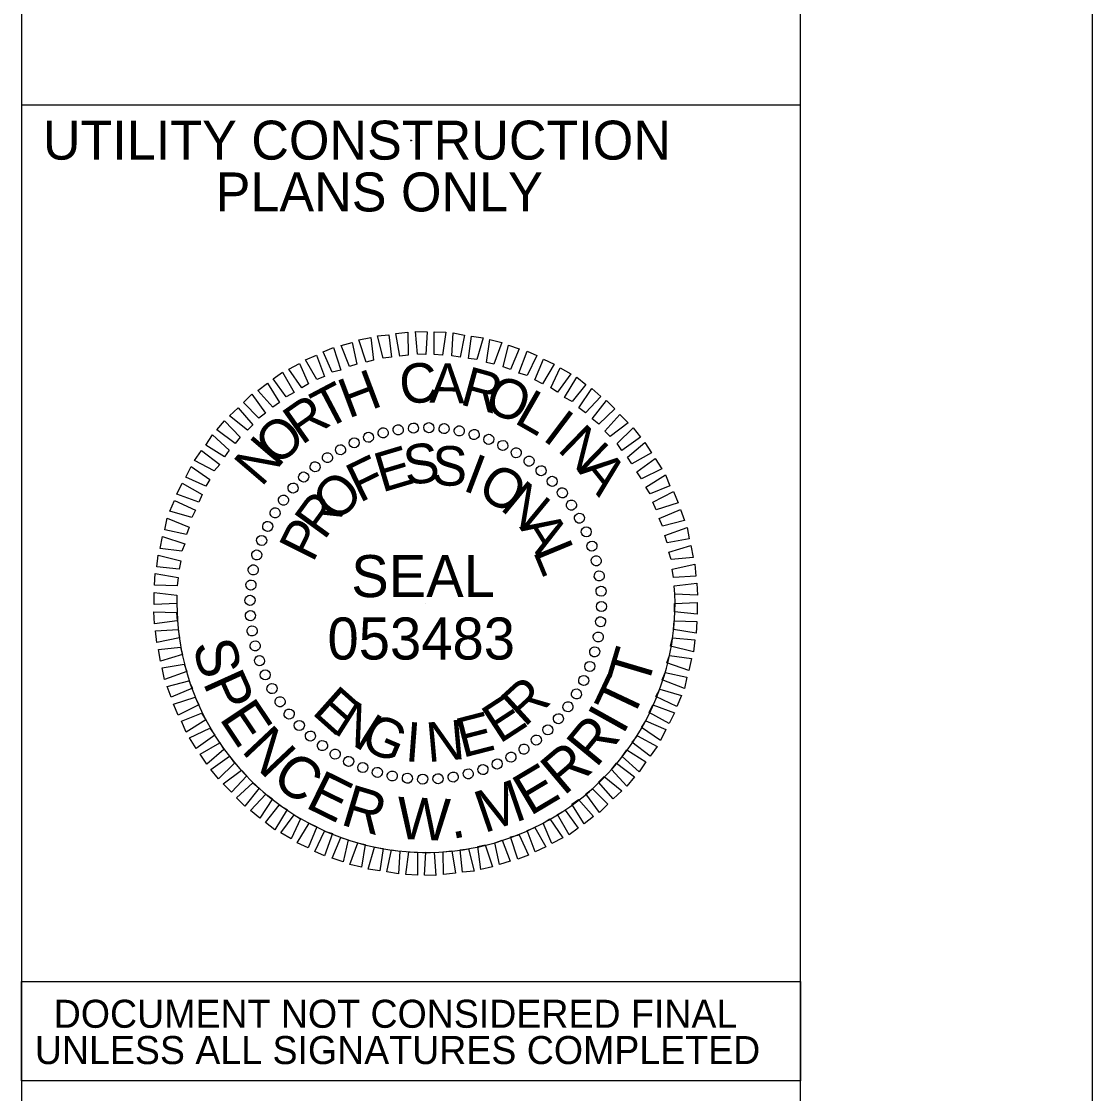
# Model space of a CAD drawing. Extents: x -0.32 to 3.05, y 0 to 1.83.
# Drawn here: x 2.6041 to 2.8333, y 1.3744 to 1.6039 of the extents above; entities that cross this region are included whole.
import ezdxf

# ---------------------------------------------------------------- set-up
doc = ezdxf.new("R2010")
doc.units = 0
for name, color, linetype in [('E_NCDOT_Terrain_Model_Contour_Minor', 7, 'Continuous'), ('P_NCDOT_Terrain_Model_Triangles', 7, 'Continuous'), ('P_RDY_TL_Draft_DNC_Null_Point', 7, 'Continuous'), ('P_RDY_TL_Grass_Shoulder_Normal', 7, 'Continuous')]:
    doc.layers.add(name, color=color, linetype=linetype)

msp = doc.modelspace()

# ---------------------------------------------------------------- linework, layer by layer
at = {"layer": 'E_NCDOT_Terrain_Model_Contour_Minor'}
msp.add_arc((2.69065, 1.4793), 0.05331, 180.0118, 2.0847, dxfattribs=at)
at = {"layer": 'P_NCDOT_Terrain_Model_Triangles'}
for p, q in [((2.68797, 1.51686), (2.68797, 1.51686)), ((2.69127, 1.51694), (2.69127, 1.51694)), ((2.6783, 1.51491), (2.6783, 1.51491)), ((2.68145, 1.51581), (2.68145, 1.51581)), ((2.68475, 1.51641), (2.68475, 1.51641)), ((2.69457, 1.51671), (2.69457, 1.51671)), ((2.6978, 1.51619), (2.6978, 1.51619)), ((2.70095, 1.51551), (2.70095, 1.51551)), ((2.6753, 1.51371), (2.6753, 1.51371)), ((2.7041, 1.51446), (2.7041, 1.51446)), ((2.7071, 1.51311), (2.7071, 1.51311)), ((2.66952, 1.51049), (2.66952, 1.51049)), ((2.67237, 1.51221), (2.67237, 1.51221)), ((2.71002, 1.51161), (2.71002, 1.51161)), ((2.6669, 1.50861), (2.6669, 1.50861)), ((2.71272, 1.50974), (2.71272, 1.50974)), ((2.71535, 1.50771), (2.71535, 1.50771)), ((2.66442, 1.50636), (2.66442, 1.50636)), ((2.71767, 1.50546), (2.71767, 1.50546)), ((2.66217, 1.50404), (2.66217, 1.50404)), ((2.66015, 1.50141), (2.66015, 1.50141)), ((2.71992, 1.50299), (2.71992, 1.50299)), ((2.65827, 1.49871), (2.65827, 1.49871)), ((2.7218, 1.50036), (2.7218, 1.50036)), ((2.72352, 1.49751), (2.72352, 1.49751)), ((2.65677, 1.49579), (2.65677, 1.49579)), ((2.72502, 1.49459), (2.72502, 1.49459)), ((2.65542, 1.49279), (2.65542, 1.49279)), ((2.72622, 1.49159), (2.72622, 1.49159)), ((2.65437, 1.48964), (2.65437, 1.48964)), ((2.72712, 1.48844), (2.72712, 1.48844)), ((2.6537, 1.48649), (2.6537, 1.48649)), ((2.72772, 1.48514), (2.72772, 1.48514)), ((2.65317, 1.48326), (2.65317, 1.48326)), ((2.72817, 1.48191), (2.72817, 1.48191)), ((2.65295, 1.47996), (2.65295, 1.47996)), ((2.6906, 1.47929), (2.6906, 1.47929)), ((2.72825, 1.47861), (2.72825, 1.47861)), ((2.65302, 1.47666), (2.65302, 1.47666)), ((2.65347, 1.47344), (2.65347, 1.47344)), ((2.72802, 1.47531), (2.72802, 1.47531)), ((2.7275, 1.47209), (2.7275, 1.47209)), ((2.65407, 1.47014), (2.65407, 1.47014)), ((2.72682, 1.46894), (2.72682, 1.46894)), ((2.65497, 1.46699), (2.65497, 1.46699)), ((2.72577, 1.46579), (2.72577, 1.46579)), ((2.65617, 1.46399), (2.65617, 1.46399)), ((2.72442, 1.46279), (2.72442, 1.46279)), ((2.65767, 1.46106), (2.65767, 1.46106)), ((2.72292, 1.45986), (2.72292, 1.45986)), ((2.6594, 1.45821), (2.6594, 1.45821)), ((2.72105, 1.45716), (2.72105, 1.45716)), ((2.66127, 1.45559), (2.66127, 1.45559)), ((2.66352, 1.45311), (2.66352, 1.45311)), ((2.71902, 1.45454), (2.71902, 1.45454)), ((2.66585, 1.45086), (2.66585, 1.45086)), ((2.71677, 1.45221), (2.71677, 1.45221)), ((2.66847, 1.44884), (2.66847, 1.44884)), ((2.71167, 1.44809), (2.71167, 1.44809)), ((2.7143, 1.44996), (2.7143, 1.44996)), ((2.67117, 1.44696), (2.67117, 1.44696)), ((2.70882, 1.44636), (2.70882, 1.44636)), ((2.6741, 1.44546), (2.6741, 1.44546)), ((2.6771, 1.44411), (2.6771, 1.44411)), ((2.7029, 1.44366), (2.7029, 1.44366)), ((2.7059, 1.44486), (2.7059, 1.44486)), ((2.68025, 1.44306), (2.68025, 1.44306)), ((2.6834, 1.44239), (2.6834, 1.44239)), ((2.68662, 1.44186), (2.68662, 1.44186)), ((2.68992, 1.44164), (2.68992, 1.44164)), ((2.69322, 1.44171), (2.69322, 1.44171)), ((2.69645, 1.44216), (2.69645, 1.44216)), ((2.69975, 1.44276), (2.69975, 1.44276))]:
    msp.add_line(p, q, dxfattribs=at)
for points in [[(2.6888, 1.53261), (2.68842, 1.53749), (2.6909, 1.53741), (2.6906, 1.53254)], [(2.67785, 1.53096), (2.67627, 1.53569), (2.67882, 1.53621), (2.67942, 1.53134)], [(2.68145, 1.53179), (2.68025, 1.53659), (2.68272, 1.53681), (2.68325, 1.53201)], [(2.68505, 1.53224), (2.68422, 1.53704), (2.68677, 1.53734), (2.68685, 1.53246)], [(2.6924, 1.53254), (2.6924, 1.53741), (2.69487, 1.53734), (2.6942, 1.53246)], [(2.69615, 1.53231), (2.69645, 1.53719), (2.69892, 1.53674), (2.69795, 1.53201)], [(2.69975, 1.53171), (2.70042, 1.53651), (2.7029, 1.53614), (2.70155, 1.53149)], [(2.70357, 1.53089), (2.70432, 1.53576), (2.70687, 1.53516), (2.70515, 1.53051)], [(2.67057, 1.52879), (2.66862, 1.53314), (2.67087, 1.53404), (2.67245, 1.52924)], [(2.67425, 1.52999), (2.67252, 1.53449), (2.67485, 1.53516), (2.67582, 1.53051)], [(2.70717, 1.52991), (2.7083, 1.53456), (2.71062, 1.53381), (2.70875, 1.52939)], [(2.71055, 1.52856), (2.71227, 1.53329), (2.71437, 1.53239), (2.71227, 1.52804)], [(2.66405, 1.52541), (2.66127, 1.52946), (2.6636, 1.53066), (2.66547, 1.52631)], [(2.66727, 1.52721), (2.66487, 1.53141), (2.6672, 1.53246), (2.66892, 1.52789)], [(2.71392, 1.52714), (2.7158, 1.53156), (2.71812, 1.53051), (2.71557, 1.52631)], [(2.66075, 1.52354), (2.65797, 1.52736), (2.65992, 1.52879), (2.6624, 1.52444)], [(2.71737, 1.52541), (2.7194, 1.52969), (2.72165, 1.52841), (2.7188, 1.52451)], [(2.6579, 1.52129), (2.65467, 1.52489), (2.6567, 1.52646), (2.65932, 1.52226)], [(2.7203, 1.52339), (2.72292, 1.52774), (2.72487, 1.52616), (2.72195, 1.52249)], [(2.6549, 1.51896), (2.6516, 1.52226), (2.6534, 1.52406), (2.65632, 1.52001)], [(2.72337, 1.52114), (2.72615, 1.52526), (2.7281, 1.52361), (2.7248, 1.52009)], [(2.72622, 1.51881), (2.7293, 1.52271), (2.7311, 1.52091), (2.72765, 1.51769)], [(2.65242, 1.51634), (2.6486, 1.51941), (2.65047, 1.52114), (2.65362, 1.51754)], [(2.72892, 1.51619), (2.73215, 1.51971), (2.73395, 1.51791), (2.73005, 1.51499)], [(2.6498, 1.51349), (2.6459, 1.51641), (2.64755, 1.51836), (2.65085, 1.51484)], [(2.73155, 1.51349), (2.735, 1.51686), (2.73657, 1.51484), (2.7326, 1.51199)], [(2.64755, 1.51064), (2.6435, 1.51319), (2.64492, 1.51536), (2.64852, 1.51206)], [(2.7338, 1.51056), (2.73747, 1.51371), (2.7389, 1.51154), (2.7347, 1.50914)], [(2.6453, 1.50764), (2.6411, 1.50989), (2.6426, 1.51199), (2.6465, 1.50899)], [(2.73575, 1.50749), (2.73972, 1.51034), (2.74115, 1.50809), (2.7368, 1.50599)], [(2.6435, 1.50441), (2.63922, 1.50629), (2.64035, 1.50861), (2.6444, 1.50584)], [(2.7377, 1.50419), (2.7419, 1.50681), (2.74287, 1.50449), (2.7386, 1.50276)], [(2.642, 1.50096), (2.63735, 1.50269), (2.63847, 1.50501), (2.64275, 1.50261)], [(2.7392, 1.50096), (2.74362, 1.50321), (2.7446, 1.50081), (2.73995, 1.49931)], [(2.6405, 1.49766), (2.63585, 1.49901), (2.63682, 1.50134), (2.64132, 1.49924)], [(2.74055, 1.49744), (2.74512, 1.49939), (2.74595, 1.49706), (2.7413, 1.49586)], [(2.63937, 1.49406), (2.63472, 1.49504), (2.63525, 1.49751), (2.63997, 1.49564)], [(2.74175, 1.49384), (2.74655, 1.49556), (2.747, 1.49309), (2.74227, 1.49226)], [(2.6384, 1.49046), (2.63375, 1.49106), (2.63427, 1.49361), (2.639, 1.49204)], [(2.74265, 1.49024), (2.74737, 1.49166), (2.74782, 1.48911), (2.7431, 1.48866)], [(2.6378, 1.48664), (2.633, 1.48709), (2.6333, 1.48964), (2.63817, 1.48844)], [(2.74332, 1.48664), (2.7482, 1.48769), (2.74842, 1.48514), (2.74362, 1.48484)], [(2.63742, 1.48304), (2.63255, 1.48319), (2.6327, 1.48566), (2.63757, 1.48484)], [(2.74377, 1.48304), (2.74865, 1.48364), (2.7488, 1.48109), (2.74392, 1.48124)], [(2.63735, 1.47929), (2.63247, 1.47906), (2.63247, 1.48161), (2.63735, 1.48109)], [(2.74385, 1.47929), (2.74872, 1.47951), (2.74872, 1.47696), (2.74385, 1.47749)], [(2.63742, 1.47554), (2.63255, 1.47494), (2.6324, 1.47749), (2.63727, 1.47734)], [(2.74377, 1.47554), (2.74865, 1.47539), (2.7485, 1.47291), (2.74362, 1.47374)], [(2.63787, 1.47194), (2.633, 1.47089), (2.63277, 1.47344), (2.63757, 1.47374)], [(2.7434, 1.47194), (2.7482, 1.47149), (2.7479, 1.46894), (2.74302, 1.47014)], [(2.63855, 1.46834), (2.63382, 1.46691), (2.63337, 1.46946), (2.6381, 1.46991)], [(2.7428, 1.46811), (2.74745, 1.46751), (2.74692, 1.46496), (2.7422, 1.46654)], [(2.63945, 1.46474), (2.63465, 1.46301), (2.6342, 1.46549), (2.63892, 1.46631)], [(2.74182, 1.46451), (2.74647, 1.46354), (2.74595, 1.46106), (2.74122, 1.46294)], [(2.64065, 1.46114), (2.63607, 1.45919), (2.63525, 1.46151), (2.6399, 1.46271)], [(2.7407, 1.46091), (2.74535, 1.45956), (2.74437, 1.45724), (2.73987, 1.45934)], [(2.642, 1.45761), (2.63757, 1.45536), (2.6366, 1.45776), (2.64125, 1.45926)], [(2.7392, 1.45761), (2.74385, 1.45589), (2.74272, 1.45356), (2.73845, 1.45596)], [(2.6435, 1.45439), (2.6393, 1.45176), (2.63832, 1.45409), (2.6426, 1.45581)], [(2.64545, 1.45109), (2.64147, 1.44824), (2.64005, 1.45049), (2.6444, 1.45259)], [(2.7377, 1.45416), (2.74197, 1.45229), (2.74085, 1.44996), (2.7368, 1.45274)], [(2.7359, 1.45094), (2.7401, 1.44869), (2.7386, 1.44659), (2.7347, 1.44959)], [(2.6474, 1.44801), (2.64372, 1.44486), (2.6423, 1.44704), (2.6465, 1.44944)], [(2.64965, 1.44509), (2.6462, 1.44171), (2.64462, 1.44374), (2.6486, 1.44659)], [(2.73365, 1.44794), (2.7377, 1.44539), (2.73627, 1.44321), (2.73267, 1.44651)], [(2.65227, 1.44239), (2.64905, 1.43886), (2.64725, 1.44066), (2.65115, 1.44359)], [(2.7314, 1.44509), (2.7353, 1.44216), (2.73365, 1.44021), (2.73035, 1.44374)], [(2.72877, 1.44224), (2.7326, 1.43916), (2.73072, 1.43744), (2.72757, 1.44104)], [(2.65497, 1.43976), (2.6519, 1.43586), (2.6501, 1.43766), (2.65355, 1.44089)], [(2.7263, 1.43961), (2.7296, 1.43631), (2.7278, 1.43451), (2.72487, 1.43856)], [(2.65782, 1.43744), (2.65505, 1.43331), (2.6531, 1.43496), (2.6564, 1.43849)], [(2.7233, 1.43729), (2.72652, 1.43369), (2.7245, 1.43211), (2.72187, 1.43631)], [(2.6609, 1.43519), (2.65827, 1.43084), (2.65632, 1.43241), (2.65925, 1.43609)], [(2.72045, 1.43504), (2.72322, 1.43121), (2.72127, 1.42979), (2.7188, 1.43414)], [(2.66382, 1.43316), (2.6618, 1.42889), (2.65955, 1.43016), (2.6624, 1.43406)], [(2.66727, 1.43144), (2.6654, 1.42701), (2.66307, 1.42806), (2.66562, 1.43226)], [(2.71715, 1.43316), (2.71992, 1.42911), (2.7176, 1.42791), (2.71572, 1.43226)], [(2.67065, 1.43001), (2.66892, 1.42529), (2.66682, 1.42619), (2.66892, 1.43054)], [(2.71062, 1.42979), (2.71257, 1.42544), (2.71032, 1.42454), (2.70875, 1.42934)], [(2.71392, 1.43136), (2.71632, 1.42716), (2.714, 1.42611), (2.71227, 1.43069)], [(2.67402, 1.42866), (2.6729, 1.42401), (2.67057, 1.42476), (2.67245, 1.42919)], [(2.67762, 1.42769), (2.67687, 1.42281), (2.67432, 1.42341), (2.67605, 1.42806)], [(2.70335, 1.42761), (2.70492, 1.42289), (2.70237, 1.42236), (2.70177, 1.42724)], [(2.70695, 1.42859), (2.70867, 1.42409), (2.70635, 1.42341), (2.70537, 1.42806)], [(2.68145, 1.42686), (2.68077, 1.42206), (2.6783, 1.42244), (2.67965, 1.42709)], [(2.68505, 1.42626), (2.68475, 1.42139), (2.68227, 1.42184), (2.68325, 1.42656)], [(2.6888, 1.42604), (2.6888, 1.42116), (2.68632, 1.42124), (2.687, 1.42611)], [(2.6924, 1.42596), (2.69277, 1.42109), (2.6903, 1.42116), (2.6906, 1.42604)], [(2.69615, 1.42634), (2.69697, 1.42154), (2.69442, 1.42124), (2.69435, 1.42611)], [(2.69975, 1.42679), (2.70095, 1.42199), (2.69847, 1.42176), (2.69795, 1.42656)]]:
    msp.add_lwpolyline(points, close=True, dxfattribs=at)
for centre, major_axis in [((2.68149, 1.51579), (-0.00026, 0.00105)), ((2.68471, 1.51645), (-0.00017, 0.00107)), ((2.68797, 1.51682), (-0.00008, 0.00108)), ((2.69125, 1.5169), (0.00002, 0.00108)), ((2.69453, 1.5167), (0.00011, 0.00107)), ((2.69777, 1.51622), (0.00021, 0.00106)), ((2.67529, 1.51366), (-0.000439, 0.000987)), ((2.67835, 1.51486), (-0.00035, 0.00102)), ((2.70096, 1.51545), (0.0003, 0.00104)), ((2.70408, 1.51441), (0.00039, 0.00101)), ((2.67236, 1.51219), (-0.000524, 0.000945)), ((2.70709, 1.5131), (0.000473, 0.000971)), ((2.70997, 1.51154), (0.000556, 0.000926)), ((2.66956, 1.51048), (-0.000604, 0.000895)), ((2.71271, 1.50972), (0.000635, 0.000874)), ((2.66692, 1.50853), (-0.00068, 0.000839)), ((2.71528, 1.50768), (0.000709, 0.000815)), ((2.66446, 1.50635), (-0.00075, 0.000777)), ((2.71766, 1.50542), (0.000777, 0.00075)), ((2.6622, 1.50397), (-0.000815, 0.000709)), ((2.71983, 1.50296), (0.000839, 0.00068)), ((2.66016, 1.5014), (-0.000874, 0.000635)), ((2.72178, 1.50033), (0.000895, 0.000604)), ((2.65835, 1.49867), (-0.000926, 0.000556)), ((2.7235, 1.49753), (0.000945, 0.000524)), ((2.65678, 1.49578), (-0.000971, 0.000473)), ((2.65547, 1.49277), (-0.00101, 0.00039)), ((2.72496, 1.49459), (0.000987, 0.000439)), ((2.72617, 1.49154), (0.00102, 0.00035)), ((2.65443, 1.48966), (-0.00104, 0.0003)), ((2.7271, 1.48839), (0.00105, 0.00026)), ((2.65367, 1.48647), (-0.00106, 0.00021)), ((2.72775, 1.48517), (0.00107, 0.00017)), ((2.65318, 1.48322), (-0.00107, 0.00011)), ((2.72812, 1.48191), (0.00108, 0.00008)), ((2.65298, 1.47995), (-0.00108, 0.00002)), ((2.72821, 1.47863), (0.00108, -0.00002)), ((2.65307, 1.47667), (-0.00108, -0.00008)), ((2.72801, 1.47536), (0.00107, -0.00011)), ((2.65344, 1.4734), (-0.00107, -0.00017)), ((2.72752, 1.47211), (0.00106, -0.00021)), ((2.65409, 1.47019), (-0.00105, -0.00026)), ((2.72676, 1.46892), (0.00104, -0.0003)), ((2.65502, 1.46704), (-0.00102, -0.00035)), ((2.72572, 1.46581), (0.00101, -0.00039)), ((2.65623, 1.46399), (-0.000987, -0.000439)), ((2.65769, 1.46105), (-0.000945, -0.000524)), ((2.72441, 1.4628), (0.000971, -0.000473)), ((2.65941, 1.45825), (-0.000895, -0.000604)), ((2.72284, 1.45991), (0.000926, -0.000556)), ((2.72103, 1.45718), (0.000874, -0.000635)), ((2.66136, 1.45561), (-0.000839, -0.00068)), ((2.71899, 1.45461), (0.000815, -0.000709)), ((2.66353, 1.45316), (-0.000777, -0.00075)), ((2.71673, 1.45223), (0.00075, -0.000777)), ((2.66591, 1.4509), (-0.000709, -0.000815)), ((2.71427, 1.45005), (0.00068, -0.000839)), ((2.66848, 1.44885), (-0.000635, -0.000874)), ((2.67122, 1.44704), (-0.000556, -0.000926)), ((2.71163, 1.4481), (0.000604, -0.000895)), ((2.6741, 1.44548), (-0.000473, -0.000971)), ((2.7059, 1.44492), (0.000439, -0.000987)), ((2.70883, 1.44639), (0.000524, -0.000945)), ((2.67711, 1.44417), (-0.00039, -0.00101)), ((2.68023, 1.44313), (-0.0003, -0.00104)), ((2.68342, 1.44236), (-0.00021, -0.00106)), ((2.6997, 1.44279), (0.00026, -0.00105)), ((2.70284, 1.44372), (0.00035, -0.00102)), ((2.68666, 1.44188), (-0.00011, -0.00107)), ((2.68994, 1.44168), (-0.00002, -0.00108)), ((2.69322, 1.44176), (0.00008, -0.00108)), ((2.69648, 1.44213), (0.00017, -0.00107))]:
    msp.add_ellipse(centre, major_axis=major_axis, ratio=0.999708, dxfattribs=at)
at = {"layer": 'P_RDY_TL_Draft_DNC_Null_Point'}
msp.add_line((2.83333, 0), (2.83333, 1.83333), dxfattribs=at)
at = {"layer": 'P_RDY_TL_Grass_Shoulder_Normal'}
for p, q in [((2.60412, 0.0625), (2.60416, 1.77083)), ((2.77079, 0.0625), (2.77083, 1.77083)), ((2.77083, 1.58597), (2.60406, 1.58597)), ((2.77082, 1.3771), (2.60405, 1.3771)), ((2.77082, 1.3771), (2.60405, 1.3771))]:
    msp.add_line(p, q, dxfattribs=at)
msp.add_lwpolyline([(2.60405, 1.39834), (2.77084, 1.39834), (2.77084, 1.3771), (2.60405, 1.3771)], close=True, dxfattribs=at)
msp.add_circle((2.68745, 1.57837), 0.0001, dxfattribs=at)

# ---------------------------------------------------------------- texts
at = {"layer": 'P_NCDOT_Terrain_Model_Triangles'}
for s, height, rotation, p in [('C', 0.00846, 6.2199, (2.68542, 1.52181)), ('A', 0.00846, 359.0203, (2.69135, 1.52226)), ('H', 0.00846, 20.6195, (2.67402, 1.51881)), ('R', 0.00846, 344.6211, (2.69765, 1.52196)), ('T', 0.00846, 27.8198, (2.66915, 1.51634)), ('O', 0.00846, 337.4212, (2.70267, 1.52084)), ('L', 0.00846, 330.2209, (2.70927, 1.51806)), ('R', 0.00846, 35.0205, (2.66405, 1.51304)), ('I', 0.00846, 323.0201, (2.71535, 1.51446)), ('O', 0.00846, 42.2217, (2.65887, 1.50839)), ('N', 0.00846, 315.8189, (2.71857, 1.51214)), ('N', 0.00846, 49.4235, (2.65542, 1.50404)), ('E', 0.00846, 16.6111, (2.68122, 1.50299)), ('S', 0.00846, 7.2556, (2.6864, 1.50456)), ('S', 0.00846, 357.9004, (2.6918, 1.50464)), ('F', 0.00846, 25.967, (2.67642, 1.50074)), ('I', 0.00846, 339.1896, (2.69825, 1.50359)), ('A', 0.00846, 308.6172, (2.723, 1.50771)), ('O', 0.00846, 329.8335, (2.70125, 1.50254)), ('O', 0.00846, 44.6812, (2.67147, 1.49631)), ('N', 0.00846, 320.4766, (2.70627, 1.49954)), ('R', 0.00846, 54.0397, (2.66885, 1.49264)), ('P', 0.00846, 63.3989, (2.66645, 1.48784)), ('A', 0.00846, 301.7603, (2.71055, 1.49564)), ('L', 0.00846, 292.4009, (2.71347, 1.49046)), ('SEAL', 0.008997, 360, (2.67465, 1.48064)), ('S', 0.009, 284.7638, (2.64065, 1.47046)), ('T', 0.009, 73.4708, (2.73797, 1.46088)), ('P', 0.009, 294.2618, (2.64279, 1.46233)), ('T', 0.009, 64.7726, (2.73464, 1.45394)), ('R', 0.00846, 42.4814, (2.71175, 1.45266)), ('E', 0.00846, 318.2769, (2.666, 1.45581)), ('E', 0.00846, 33.1241, (2.70642, 1.44914)), ('E', 0.009, 303.7599, (2.64625, 1.45467)), ('N', 0.00846, 327.634, (2.6705, 1.45176)), ('I', 0.009, 60.8196, (2.73279, 1.45096)), ('G', 0.00846, 336.9902, (2.6762, 1.44839)), ('E', 0.00846, 14.4118, (2.69847, 1.44621)), ('N', 0.009, 313.2579, (2.65092, 1.44768)), ('I', 0.00846, 355.7012, (2.68602, 1.44554)), ('N', 0.00846, 5.0564, (2.69105, 1.44531)), ('R', 0.009, 50.5372, (2.72705, 1.4439)), ('R', 0.009, 40.2548, (2.72015, 1.43797)), ('C', 0.009, 323.5403, (2.6572, 1.44109)), ('E', 0.009, 30.7567, (2.71293, 1.43367)), ('E', 0.009, 333.8228, (2.66456, 1.43574)), ('M', 0.009, 18.8977, (2.70307, 1.43006)), ('R', 0.009, 343.3208, (2.67211, 1.43203)), ('W', 0.009, 357.5563, (2.6843, 1.42892)), ('.', 0.009, 10.9918, (2.69618, 1.42882))]:
    msp.add_text(s, height=height, rotation=rotation, dxfattribs=at).set_placement(p)
msp.add_text('053483', height=0.008997, dxfattribs=at).set_placement((2.66956, 1.46728))
at = {"layer": 'P_RDY_TL_Grass_Shoulder_Normal'}
for s, height, p in [('UTILITY CONSTRUCTION', 0.0083386, (2.60865, 1.57428)), ('PLANS ONLY', 0.008339, (2.64563, 1.56319)), ('DOCUMENT NOT CONSIDERED FINAL', 0.0060042, (2.61097, 1.38846)), ('UNLESS ALL SIGNATURES COMPLETED', 0.0060042, (2.60692, 1.38069))]:
    msp.add_text(s, height=height, rotation=0, dxfattribs=at).set_placement(p)

doc.saveas('drawing.dxf')
